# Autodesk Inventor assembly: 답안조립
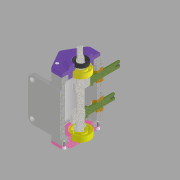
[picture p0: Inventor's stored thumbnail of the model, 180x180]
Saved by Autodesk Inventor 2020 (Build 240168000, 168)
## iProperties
Created: 2021-06
Part Number: 답안조립
Document SubType Name: Assembly
Designer: Windows7
Author: Windows7
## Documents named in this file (11)
- C:\Users\Windows7\Desktop\710606V1029\답안조립.iam
- C:\Users\Windows7\Desktop\710606V1029\본체.ipt
- C:\Users\Windows7\Desktop\710606V1029\뒷커버.ipt
- C:\Users\Windows7\Desktop\710606V1029\베어링 6203.ipt
- C:\Users\Windows7\Desktop\710606V1029\베어링 6302.ipt
- C:\Users\Windows7\Desktop\710606V1029\볼트 M4.ipt
- C:\Users\Windows7\Desktop\710606V1029\부시.ipt
- C:\Users\Windows7\Desktop\710606V1029\슬라이더.ipt
- C:\Users\Windows7\Desktop\710606V1029\앞커버.ipt
- C:\Users\Windows7\Desktop\710606V1029\오일실.ipt
- C:\Users\Windows7\Desktop\710606V1029\편심축.ipt
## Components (10 placed, 3 different names)
1. 7-베어링 6203:1
2. 8-오일실:1
3. 9-M4-소켓머리:2 — 각도:1
4. 9-M4-소켓머리:3
5. 9-M4-소켓머리:4
6. 9-M4-소켓머리:5
7. 9-M4-소켓머리:1 — 각도:2
8. 9-M4-소켓머리:6
9. 9-M4-소켓머리:7
10. 9-M4-소켓머리:8
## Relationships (2: Angle 2)
- 각도:1 [Angle]: 9-M4-소켓머리:2
- 각도:2 [Angle]: 9-M4-소켓머리:1
